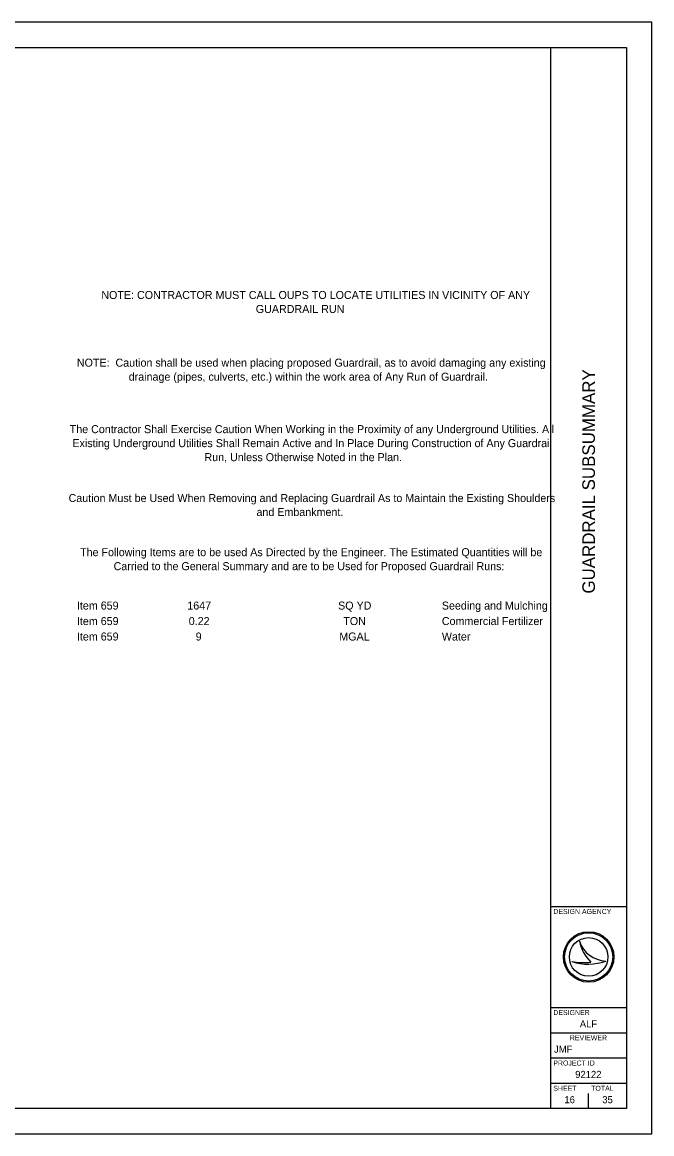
# Model space of a CAD drawing. Extents: x 0 to 680, y 0 to 440.
# Drawn here: x 430.7 to 680, y 0 to 440 of the extents above; entities that cross this region are included whole.
import ezdxf

# ---------------------------------------------------------------- set-up
doc = ezdxf.new("R2010")
doc.units = 0
for name, color, linetype in [('Default', 7, 'Continuous'), ('SH_Border', 7, 'Continuous'), ('SH_Cut_Line', 7, 'Continuous'), ('SH_Data', 7, 'Continuous')]:
    doc.layers.add(name, color=color, linetype=linetype)

msp = doc.modelspace()

# ---------------------------------------------------------------- linework, layer by layer
at = {"layer": 'SH_Border'}
for p, q in [((640, 10), (640, 430)), ((640, 90), (670, 90)), ((640, 50), (670, 50)), ((640, 40), (670, 40)), ((640, 30), (670, 30)), ((640, 20), (670, 20))]:
    msp.add_line(p, q, dxfattribs=at)
msp.add_lwpolyline([(30, 430), (670, 430), (670, 10), (30, 10)], close=True, dxfattribs=at)
at = {"layer": 'SH_Cut_Line'}
msp.add_lwpolyline([(0, 0), (680, 0), (680, 440), (0, 440)], close=True, dxfattribs=at)
at = {"layer": 'SH_Data'}
for p, q in [((651.35, 76.19), (651.35, 76.19)), ((648.34, 68.19), (648.34, 68.19)), ((655, 70), (655, 70)), ((661.75, 68.37), (661.75, 68.37)), ((647.5, 13.5), (647.5, 13.5)), ((655, 10), (655, 16))]:
    msp.add_line(p, q, dxfattribs=at)
for radius in [10, 9.54, 9.54, 7.64]:
    msp.add_circle((655, 70), radius, dxfattribs=at)
for centre, radius, start, end in [((662.32, 79.95), 11.6, 198.9257, 198.9319), ((666.93, 79.4), 15.91, 191.6379, 191.6421), ((662.32, 79.95), 11.6, 198.9319, 267.1657), ((666.93, 79.4), 15.91, 191.6421, 226.0947), ((654.79, 87.4), 20.26, 251.4576, 290.0832), ((652.96, 93.09), 25.32, 259.4964, 259.4995), ((654.79, 87.4), 20.26, 251.4527, 251.4576), ((652.96, 93.09), 25.32, 259.4995, 276.6672)]:
    msp.add_arc(centre, radius, start, end, dxfattribs=at)

# ---------------------------------------------------------------- texts
at = {"layer": 'Default'}
for s, height, p in [('   NOTE: CONTRACTOR MUST CALL OUPS TO LOCATE UTILITIES IN VICINITY OF ANY ', 3.169, (458.52, 330.45)), ('GUARDRAIL RUN', 3.169, (523.21, 324.9)), ('NOTE:  Caution shall be used when placing proposed Guardrail, as to avoid damaging any existing ', 3.169, (452.36, 303.66)), ('drainage (pipes, culverts, etc.) within the work area of Any Run of Guardrail.', 3.169, (472.89, 298.11)), ('The Contractor Shall Exercise Caution When Working in the Proximity of any Underground Utilities. All ', 3.16896, (449.53, 277.34)), ('Existing Underground Utilities Shall Remain Active and In Place During Construction of Any Guardrail ', 3.16896, (450.6, 271.8)), ('Run, Unless Otherwise Noted in the Plan.', 3.169, (502.89, 266.25)), ('Caution Must be Used When Removing and Replacing Guardrail As to Maintain the Existing Shoulders ', 3.169, (449.09, 250.07)), ('and Embankment.', 3.169, (523.48, 244.53)), ('The Following Items are to be used As Directed by the Engineer. The Estimated Quantities will be ', 3.169, (453.64, 228.64)), ('Carried to the General Summary and are to be Used for Proposed Guardrail Runs:', 3.169, (466.91, 223.1)), ('Item 659', 3.169, (452.39, 207.5)), ('1647', 3.169, (496.09, 207.5)), ('SQ YD', 3.169, (555.8, 207.5)), ('Seeding and Mulching', 3.169, (596.88, 207.5)), ('Item 659', 3.169, (452.39, 201.37)), ('0.22', 3.169, (496.66, 201.37)), ('TON', 3.169, (557.85, 201.37)), ('Commercial Fertilizer', 3.169, (596.88, 201.37)), ('Item 659', 3.169, (452.39, 195.25)), ('9', 3.17, (499.41, 195.25)), ('MGAL', 3.169, (556.28, 195.25)), ('Water', 3.169, (596.88, 195.25))]:
    msp.add_text(s, height=height, dxfattribs=at).set_placement(p)
at = {"layer": 'SH_Data'}
msp.add_text('GUARDRAIL SUBSUMMARY', height=5, rotation=90, dxfattribs=at).set_placement((657.5, 213.83))
for s, height, p in [('DESIGN AGENCY', 2, (641, 87)), ('DESIGNER', 2, (641, 47)), ('ALF', 2.8, (651.5, 42.1)), ('REVIEWER', 2, (647.57, 37)), ('JMF', 2.8, (641.29, 32.1)), ('PROJECT ID', 2, (641, 27)), ('92122', 2.8, (649.67, 22.1)), ('SHEET', 2, (641, 17)), ('TOTAL', 2, (656, 17)), ('16', 2.8, (645.41, 12.1)), ('35', 2.8, (660.4, 12.1))]:
    msp.add_text(s, height=height, dxfattribs=at).set_placement(p)

doc.saveas('drawing.dxf')
